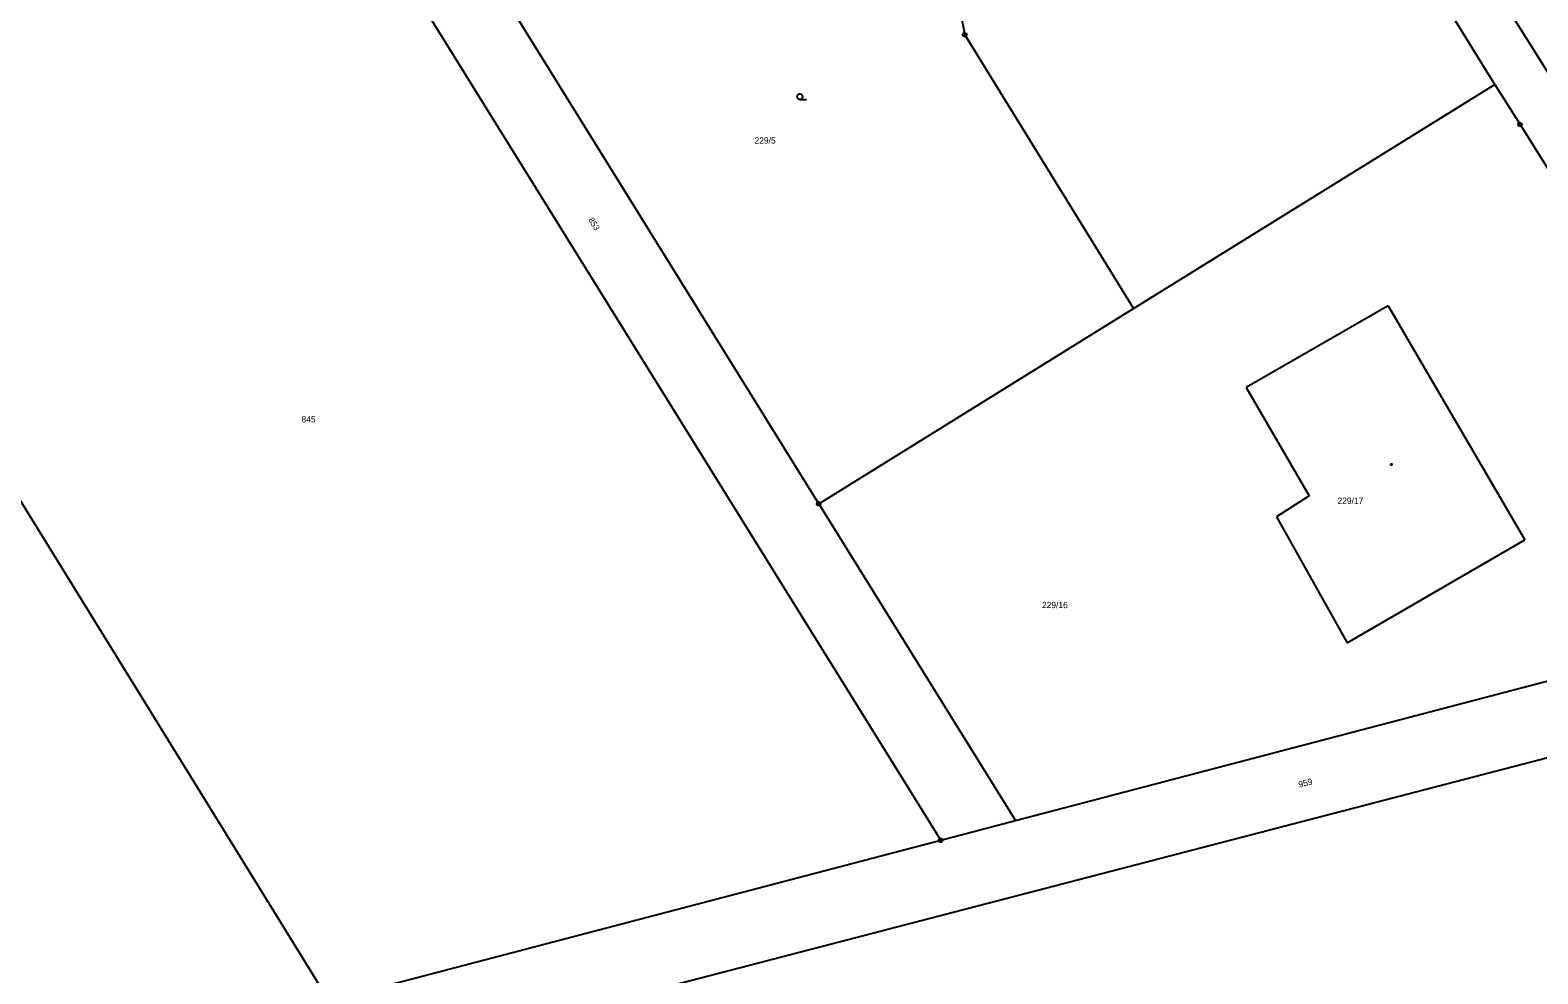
# Model space of a CAD drawing. Extents: x -871430 to -870620, y -1010094 to -1009649.
# Drawn here: x -871158.1 to -871056.6, y -1009857 to -1009793.5 of the extents above; entities that cross this region are included whole.
import ezdxf

# ---------------------------------------------------------------- set-up
doc = ezdxf.new("R2010")
doc.units = 0
for name, color, linetype in [('Vrstva 1', 7, 'Continuous'), ('Vrstva 2', 7, 'Continuous'), ('Vrstva 3', 7, 'Continuous'), ('Vrstva 4', 7, 'Continuous'), ('Vrstva 5', 7, 'Continuous'), ('Vrstva 8', 7, 'Continuous')]:
    doc.layers.add(name, color=color, linetype=linetype)

msp = doc.modelspace()

# ---------------------------------------------------------------- linework, layer by layer
at = {"layer": 'Vrstva 1'}
for p, q in [((-871096.81, -1009848.03), (-871148.38, -1009764.88)), ((-871059.52, -1009797.14), (-871074.79, -1009772.51)), ((-871183.09, -1009785.71), (-871137.99, -1009858.82)), ((-871096.7, -1009786.1), (-871095.19, -1009793.79)), ((-871105.02, -1009825.37), (-871127.8, -1009788.62)), ((-871095.19, -1009793.79), (-871083.83, -1009812.22)), ((-871083.83, -1009812.22), (-871059.52, -1009797.14)), ((-871059.52, -1009797.14), (-871057.82, -1009799.84)), ((-871057.82, -1009799.84), (-871049.86, -1009812.56)), ((-871105.02, -1009825.37), (-871083.83, -1009812.22)), ((-871066.71, -1009812.04), (-871076.26, -1009817.54)), ((-871066.71, -1009812.04), (-871057.5, -1009827.8)), ((-871076.26, -1009817.54), (-871072.02, -1009824.84)), ((-871072.02, -1009824.84), (-871074.21, -1009826.24)), ((-871105.02, -1009825.37), (-871091.79, -1009846.7)), ((-871074.21, -1009826.24), (-871071.63, -1009830.86)), ((-871069.47, -1009834.73), (-871057.5, -1009827.8)), ((-871071.63, -1009830.86), (-871069.47, -1009834.73)), ((-871091.79, -1009846.7), (-871036.48, -1009832.19)), ((-871131.99, -1009862.23), (-871048.58, -1009840.53)), ((-871096.81, -1009848.03), (-871091.79, -1009846.7)), ((-871133.93, -1009857.75), (-871096.81, -1009848.03))]:
    msp.add_line(p, q, dxfattribs=at)
at = {"layer": 'Vrstva 3'}
msp.add_lwpolyline([(-871106.29, -1009798.15), (-871106.385, -1009798.125), (-871106.452, -1009798.055), (-871106.478, -1009797.962), (-871106.452, -1009797.87), (-871106.385, -1009797.8), (-871106.29, -1009797.775), (-871106.195, -1009797.8), (-871106.128, -1009797.87), (-871106.102, -1009797.962), (-871106.128, -1009798.055), (-871106.195, -1009798.125), (-871106.29, -1009798.15), (-871105.852, -1009798.15)], dxfattribs=at)
at = {"layer": 'Vrstva 4'}
msp.add_line((-871086.33, -1009747.82), (-871017.56, -1009857.66), dxfattribs=at)
at = {"layer": 'Vrstva 5'}
msp.add_lwpolyline([(-871066.49, -1009822.688), (-871066.465, -1009822.692), (-871066.452, -1009822.715), (-871066.448, -1009822.73), (-871066.452, -1009822.752), (-871066.472, -1009822.77), (-871066.49, -1009822.772), (-871066.512, -1009822.765), (-871066.528, -1009822.75), (-871066.532, -1009822.73), (-871066.528, -1009822.708), (-871066.508, -1009822.69), (-871066.49, -1009822.688)], dxfattribs=at)
at = {"layer": 'Vrstva 8'}
for p, q in [((-871095.202, -1009793.79), (-871095.178, -1009793.79)), ((-871057.832, -1009799.84), (-871057.808, -1009799.84)), ((-871105.032, -1009825.37), (-871105.008, -1009825.37)), ((-871096.822, -1009848.03), (-871096.798, -1009848.03))]:
    msp.add_line(p, q, dxfattribs=at)
for points in [[(-871095.152, -1009793.67), (-871095.09, -1009793.718), (-871095.065, -1009793.79), (-871095.09, -1009793.862), (-871095.152, -1009793.91), (-871095.227, -1009793.91), (-871095.29, -1009793.862), (-871095.315, -1009793.79), (-871095.29, -1009793.718), (-871095.227, -1009793.67), (-871095.152, -1009793.67)], [(-871057.782, -1009799.72), (-871057.72, -1009799.768), (-871057.695, -1009799.84), (-871057.72, -1009799.912), (-871057.782, -1009799.96), (-871057.857, -1009799.96), (-871057.92, -1009799.912), (-871057.945, -1009799.84), (-871057.92, -1009799.768), (-871057.857, -1009799.72), (-871057.782, -1009799.72)], [(-871104.982, -1009825.25), (-871104.92, -1009825.298), (-871104.895, -1009825.37), (-871104.92, -1009825.442), (-871104.982, -1009825.49), (-871105.058, -1009825.49), (-871105.12, -1009825.442), (-871105.145, -1009825.37), (-871105.12, -1009825.298), (-871105.058, -1009825.25), (-871104.982, -1009825.25)], [(-871096.773, -1009847.91), (-871096.71, -1009847.958), (-871096.685, -1009848.03), (-871096.71, -1009848.102), (-871096.773, -1009848.15), (-871096.848, -1009848.15), (-871096.91, -1009848.102), (-871096.935, -1009848.03), (-871096.91, -1009847.958), (-871096.848, -1009847.91), (-871096.773, -1009847.91)]]:
    msp.add_lwpolyline(points, dxfattribs=at)

# ---------------------------------------------------------------- texts
at = {"layer": 'Vrstva 2'}
for s, p in [('229/5', (-871109.341, -1009801.12)), ('845', (-871139.827, -1009819.893)), ('229/17', (-871070.111, -1009825.38)), ('229/16', (-871090.001, -1009832.4))]:
    msp.add_text(s, height=0.425, dxfattribs=at).set_placement(p)
for s, height, rotation, p in [('853', 0.4, 301.49039, (-871120.539, -1009806.259)), ('959', 0.425, 14.49583, (-871072.677, -1009844.493))]:
    msp.add_text(s, height=height, rotation=rotation, dxfattribs=at).set_placement(p)

doc.saveas('drawing.dxf')
